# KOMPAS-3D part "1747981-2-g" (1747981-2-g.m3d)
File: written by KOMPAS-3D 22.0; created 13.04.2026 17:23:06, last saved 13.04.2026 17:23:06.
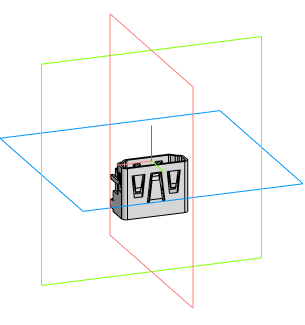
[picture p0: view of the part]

Document properties: Автор: Andrey; Полное имя файла: C:\Users\User1\Documents\1747981-2-g.m3d

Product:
- Part/product: 1747981-2-g

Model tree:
1. Операция без истории:1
